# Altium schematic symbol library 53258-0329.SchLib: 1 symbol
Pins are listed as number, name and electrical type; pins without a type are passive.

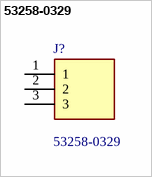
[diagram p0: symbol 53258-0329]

## 53258-0329
designator J?
Molex 53258, 3.5mm Pitch, 3 Way, 1 Row, Straight PCB Header, Through Hole; Geometry.Height: 10.5mm
footprint SHDR3W120P0X350_1X3_1260X760X1050P
pins: 1, 2, 3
